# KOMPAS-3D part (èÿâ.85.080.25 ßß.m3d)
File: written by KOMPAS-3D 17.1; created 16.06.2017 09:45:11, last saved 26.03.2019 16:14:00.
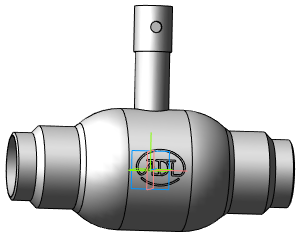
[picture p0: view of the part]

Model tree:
1. Операция без истории:2  (labels: Сталь 20  ГОСТ 1050-88)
